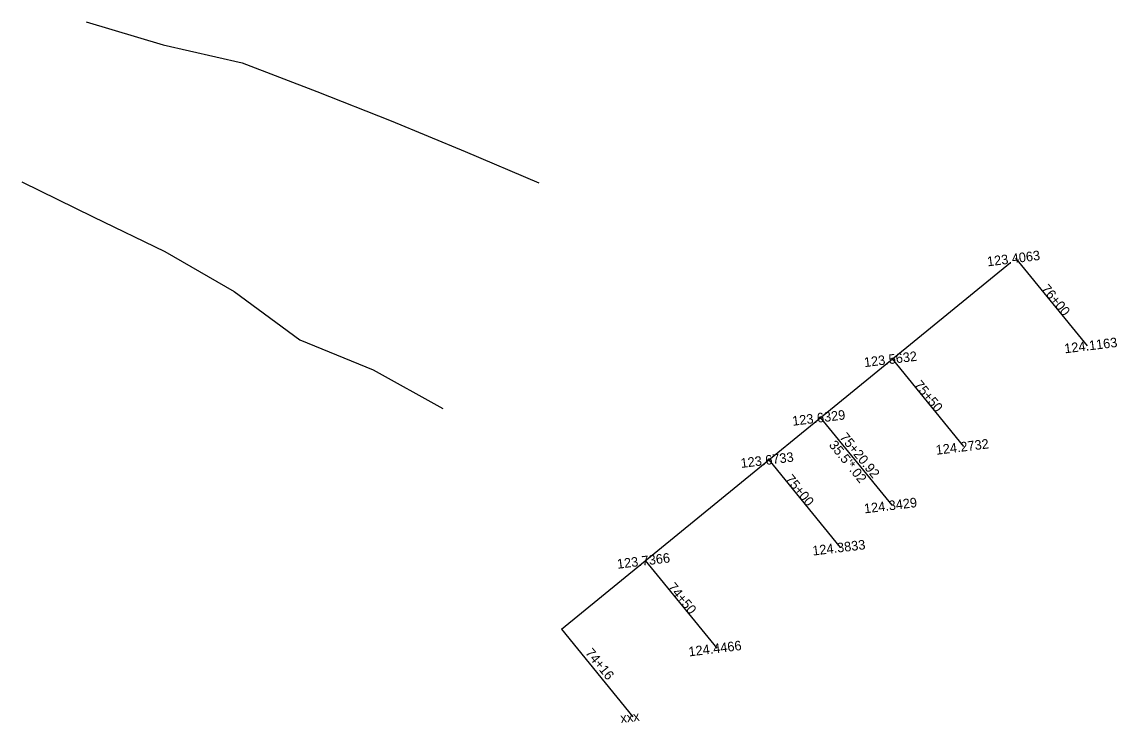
# Model space of a CAD drawing. Extents: x -26 to 2326562, y -64394 to 602094.
# Drawn here: x 2326218.6 to 2326562.4, y 601873.8 to 602093.8 of the extents above; entities that cross this region are included whole.
import ezdxf

# ---------------------------------------------------------------- set-up
doc = ezdxf.new("R2010")
doc.units = 0
doc.layers.add('Default', color=7, linetype='Continuous')
doc.layers.add('Scratch_Level_1', color=7, linetype='Continuous')

msp = doc.modelspace()

# ---------------------------------------------------------------- linework, layer by layer
at = {"layer": 'Default'}
for p, q in [((2326238.78, 602093.77), (2326262.92, 602086.55)), ((2326262.92, 602086.55), (2326287.73, 602080.94)), ((2326287.73, 602080.94), (2326311.19, 602071.97)), ((2326311.19, 602071.97), (2326334.52, 602062.71)), ((2326334.52, 602062.71), (2326357.73, 602053.14)), ((2326357.73, 602053.14), (2326380.83, 602043.31)), ((2326218.61, 602043.62), (2326241.02, 602032.61)), ((2326241.02, 602032.61), (2326263.5, 602021.8)), ((2326263.5, 602021.8), (2326285.25, 602009.24)), ((2326285.25, 602009.24), (2326305.88, 601994.05)), ((2326305.88, 601994.05), (2326328.88, 601984.6)), ((2326328.88, 601984.6), (2326350.75, 601972.49))]:
    msp.add_line(p, q, dxfattribs=at)
at = {"layer": 'Scratch_Level_1'}
for p, q in [((2326387.95, 601903.3), (2326528.87, 602018.35)), ((2326530.48, 602019.66), (2326552.93, 601992.16)), ((2326491.75, 601988.04), (2326514.2, 601960.54)), ((2326469.22, 601969.65), (2326491.67, 601942.15)), ((2326453.02, 601956.42), (2326475.47, 601928.92)), ((2326414.28, 601924.8), (2326436.73, 601897.3)), ((2326387.95, 601903.3), (2326410.4, 601875.8))]:
    msp.add_line(p, q, dxfattribs=at)

# ---------------------------------------------------------------- texts
for s, rotation, p in [('123.4063', 6.9902, (2326521.73, 602017.08)), ('76+00', 309.228, (2326538.4, 602009.96)), ('124.1163', 6.9902, (2326545.98, 601989.8)), ('123.5632', 6.9902, (2326483.11, 601985.47)), ('75+50', 309.228, (2326498.46, 601979.82)), ('123.6329', 6.9902, (2326460.59, 601967.08)), ('75+20.92', 309.228, (2326475.13, 601963.39)), ("35.5'*.02", 309.228, (2326471.75, 601960.98)), ('124.2732', 6.9902, (2326505.64, 601957.98)), ('123.6733', 6.9902, (2326444.38, 601953.85)), ('75+00', 309.228, (2326458.03, 601950.28)), ('124.3429', 6.9902, (2326483.11, 601939.59)), ('124.3833', 6.9902, (2326466.9, 601926.36)), ('123.7366', 6.9902, (2326405.58, 601922.22)), ('74+50', 309.228, (2326421.15, 601916.39)), ('124.4466', 6.9902, (2326428.03, 601894.72)), ('74+16', 309.228, (2326395.3, 601895.78)), ('xxx', 6.9902, (2326406.64, 601873.83))]:
    msp.add_text(s, height=3, rotation=rotation, dxfattribs=at).set_placement(p)

doc.saveas('drawing.dxf')
